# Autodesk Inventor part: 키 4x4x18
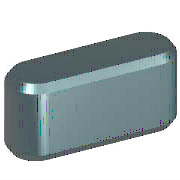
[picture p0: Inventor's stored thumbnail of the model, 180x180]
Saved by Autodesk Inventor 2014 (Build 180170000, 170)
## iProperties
IsCustomPart: 1
Created: 2012-02
Part Number: 키 4x4x18
Material: 강철, 연강
Description: 키 및 해당 키홈
Document SubType Name: Modeling
Standard: KS B 1311
Designer: mduedu
Standards Organization: KS
Language: ko-KR
Size Designation: 4 x 4 x 18
Categories: <MemberInstance><Categories><Category DisplayName="샤프트 부품" InternalName="7f7aeb1f-a693-4053-b835-cee3144e0d98" Mnemonic="SHFT"><Category DisplayName="키" Interna
Density: 7.86 g/cm^3
Mass: 2.13606 g
Surface Area: 2.87354 cm^2
Volume: 0.271763 cm^3
Appearance: 노란색
Author: mduedu
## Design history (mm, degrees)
workplane "Work Plane1"
workplane "Work Plane2"
sketch "스케치1"
  geometry: L1 (2, 2)-(16, 2); L2 (16, -2)-(2, -2); L3 (0, 9.4)-(0, -7.4) reference; L4 (-5, 0)-(30, 0) reference; L5 (18, 0)-(18, 7); A1 r 2 centre (2, 0) between (2, 2) and (2, -2); A2 r 2 centre (16, 0) between (16, -2) and (16, 2)
  constraints: 6 end point, 5 point on circle, 4 tangent, 3 point on line, 2 centre point, 1 horizontal, 1 parallel, 1 perpendicular
  dimensions: "d0" = 2 radius of A1 (= 0.5 x PB); "d13" = 2 radius of A2 (= 0.5 x PB); "d14" = 18 distance between parallel lines of L5 L3 (= NLG)
extrude "본체1" new body sketch "스케치1" taper "d3" = 0 deg; stored distance "d4" = 10
workplane "Work Plane3"
body "Solid1"
chamfer "모따기1" distance "d8" = 0.25 (= PHH); stored, may be unused: second distance "d9" = 0.25 (= PHH), angle "d15" = 45 deg
other parameters: "d1" = -2.5 (= -PNT), "d2" = 1.5 (= PH - PNT), "NLG" = 18 [user parameter; used in 3 equation terms], "PB" = 4 [user parameter; used in 2 equation terms], "PNT" = 2.5 [user parameter; used in 2 equation terms], "PH" = 4 [user parameter; used in 1 equation term], "PHH" = 0.25 [user parameter; used in 2 equation terms], "d10" = 0, "d16" = 0, "d17" = 0, "d18" = 0, "PLB2" = 18 (= NLG) [user parameter], "WDMAX" = 12 [user parameter], "PLB1" = 18 (= NLG) [user parameter], "RR" = 0.08 [user parameter], "PUEB" = 1.8 [user parameter]
